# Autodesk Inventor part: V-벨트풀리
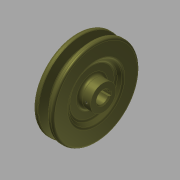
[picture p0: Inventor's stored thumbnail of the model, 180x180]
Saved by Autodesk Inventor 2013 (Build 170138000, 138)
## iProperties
Company: 한국ATC센터
Created: 2015-12
Part Number: V-벨트풀리
Document SubType Name: Modeling
Designer: mdu
Density: 7.25 g/cm^3
Mass: 594.591 g
Surface Area: 210.471 cm^2
Volume: 82.0126 cm^3
Material: 주철
Author: mdu
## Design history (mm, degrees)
sketch "스케치1"
  geometry: L1 (-13, 0)-(13, 0); L2 (-13, 0)-(-13, 12.5); L3 (-13, 12.5)-(-9, 12.5); L4 (-9, 12.5)-(-9, 23); L5 (-9, 23)-(-13, 27); L6 (-13, 27)-(-13, 42.7); L7 (-13, 42.7)-(-8.325, 42.7); L8 (-8.325, 42.7)-(-5.574, 33.7); L9 (-5.574, 33.7)-(-1.426, 33.7); L10 (-1.426, 33.7)-(1.325, 42.7); L11 (1.325, 42.7)-(6, 42.7); L12 (6, 42.7)-(6, 27); L13 (6, 27)-(2, 23); L14 (2, 23)-(2, 12.5); L15 (2, 12.5)-(13, 12.5); L16 (13, 12.5)-(13, 0); L17 (-7.5, 40)-(0.5, 40); 2 further points
  constraints: 34 end point, 6 parallel, 5 collinear, 5 equal length, 4 perpendicular, 2 point on line, 1 coincident, 1 horizontal, 1 midpoint
  dimensions: "d0" = 26 distance of L1.start L1.end; "d1" = 2.7 distance between parallel lines of L7 L17; "d2" = 6.3 distance between parallel lines of L9 L17; "d3" = 8 distance of L17.start L17.end; "d4" = 34 deg angle of L10 L8; "d5" = 19 distance between parallel lines of L12 L6; "d7" = 25 diameter of L15 L1; "d8" = 46 diameter of L13.end L1; "d9" = 54 diameter of L12.end L1; "d10" = 4 distance between parallel lines of L2 L4; "d11" = 80 diameter of L17 L1
revolve "회전1" sketch "스케치1" stored, may be unused: angle "d12" = 90 deg
sketch "스케치2"
  geometry: L1 (-2, 5.657)-(-2, 7.8); L2 (-2, 7.8)-(2, 7.8); L3 (2, 7.8)-(2, 5.657); A1 r 6 centre (0, 0) between (-2, 5.657) and (2, 5.657); 1 further point
  constraints: 6 end point, 2 parallel, 2 point on circle, 1 centre point, 1 coincident, 1 perpendicular, 1 vertical
  dimensions: "d13" = 12 diameter of A1; "d14" = 13.8 dimension on A1 L2; "d15" = 4 distance of L1.end L2.end
extrude "돌출1" cut sketch "스케치2" stored distance "d16" = 10; taper "d17" = 0 deg
node "작업 평면1"
sketch "스케치3"
  geometry: L1 (-5.5, 12.5)-(-5.5, -12.5) reference; L2 (20.5, 27)-(20.5, -27) reference; 3 further points
  constraints: 1 horizontal alignment, 1 midpoint
  dimensions: "d18" = 4 distance from line of point (-1.5, 0) L1; "d33" = 22 distance from line of point (-1.5, 0) L2 (derived)
hole "구멍1" sketch "스케치3" at (-1.5, 0) diameter "d19" = 2.459; stored, may be unused: countersink angle "d23" = 90 deg, drill point angle "d25" = 118 deg; dims "d20" = 6, "d21" = 4, "d22" = 2, "d24" = 8
fillet "모깎기1" dims "d26" = 2, "d27" = 0.5, "d28" = 1, "d29" = 3
chamfer "모따기1" distance "d30" = 1; stored, may be unused: second distance "d31" = 2, angle "d32" = 45 deg
node "솔리드1"
